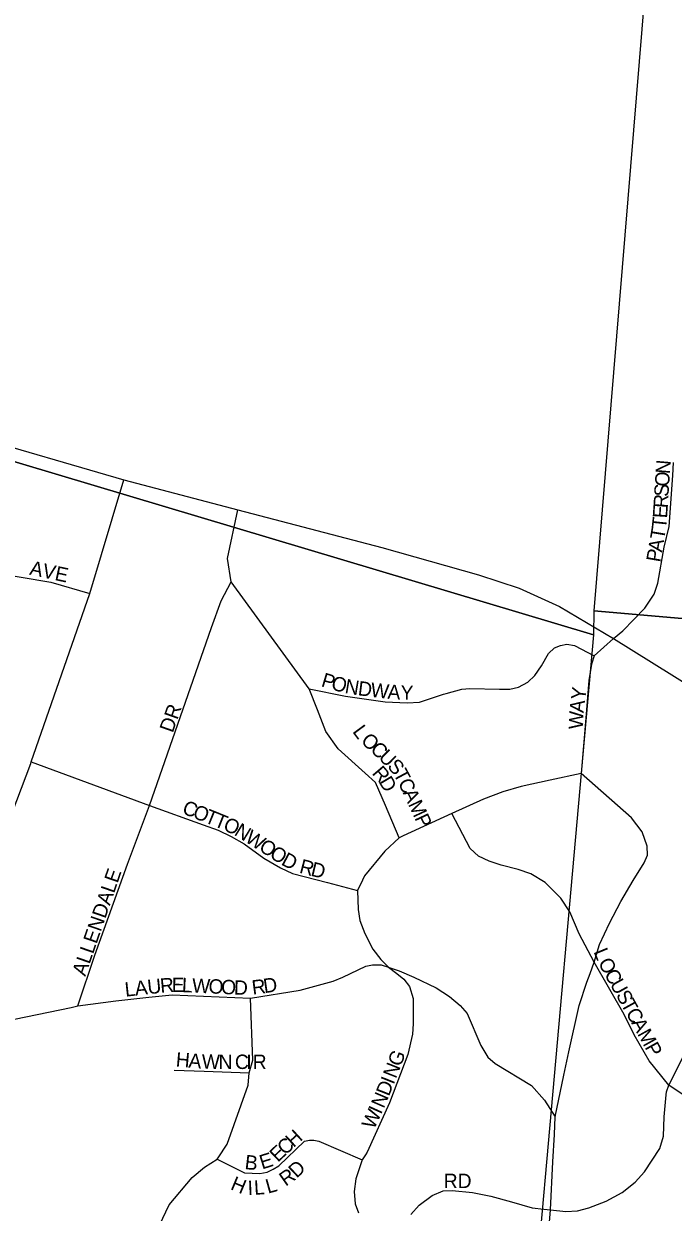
# Model space of a CAD drawing. Extents: x -209 to 4852, y 0 to 905.
# Drawn here: x 550.64 to 559.18, y 296.95 to 312.57 of the extents above; entities that cross this region are included whole.
import ezdxf

# ---------------------------------------------------------------- set-up
doc = ezdxf.new("R2010")
doc.units = 0
for name, color, linetype in [('GM_X_Airport_Location_Class_2', 7, 'Continuous'), ('GM_X_Airport_Location_Class_3', 7, 'Continuous'), ('GM_X_Minor_River', 7, 'Continuous')]:
    doc.layers.add(name, color=color, linetype=linetype)

msp = doc.modelspace()

# ---------------------------------------------------------------- linework, layer by layer
at = {"layer": 'GM_X_Airport_Location_Class_2'}
for points in [[(548.525, 307.589), (549.899, 307.171), (551.953, 306.575), (553.454, 306.181), (555.347, 305.684), (556.618, 305.327), (557.153, 305.149), (557.685, 304.91), (558.396, 304.487), (559.431, 303.846), (559.696, 303.716), (560.044, 303.613), (560.449, 303.573), (560.766, 303.576), (560.976, 303.613), (561.85, 303.84), (563.185, 304.193), (563.947, 304.283), (565.028, 304.262), (565.129, 304.259), (566.117, 304.211), (567.878, 304.065), (568.882, 303.995), (570.26, 303.866)], [(558.396, 304.487), (558.519, 304.587), (558.806, 304.885), (558.931, 305.069), (558.977, 305.215), (559.059, 305.688), (559.125, 305.96), (559.176, 306.632), (559.183, 306.8)], [(550.727, 302.846), (550.735, 302.866), (551.505, 305.081), (551.953, 306.575)], [(551.347, 299.657), (551.572, 300.324), (552, 301.522), (552.288, 302.293), (552.898, 304.039), (553.106, 304.634), (553.231, 304.985), (553.363, 305.232), (553.316, 305.54), (553.454, 306.181)], [(544.594, 304.586), (545.72, 304.515), (546.39, 304.501), (546.876, 304.584), (547.477, 304.777), (548.049, 305.045), (548.495, 305.231), (548.976, 305.321), (549.499, 305.381), (550.207, 305.361), (550.992, 305.229), (551.505, 305.081)], [(555.573, 301.869), (555.395, 302.294), (555.262, 302.597), (555.129, 302.717), (554.771, 303.036), (554.609, 303.264), (554.501, 303.55), (554.391, 303.826), (553.363, 305.232)], [(558.396, 304.487), (558.141, 304.261), (558.104, 304.152), (558.071, 303.936), (558.029, 303.44), (557.969, 302.715), (557.563, 302.627), (557.181, 302.543), (556.94, 302.473), (556.686, 302.378), (556.268, 302.188), (555.625, 301.893)], [(556.193, 303.765), (556.399, 303.82), (556.504, 303.831), (556.894, 303.82), (557.029, 303.82), (557.143, 303.848), (557.267, 303.915), (557.359, 304), (557.445, 304.127), (557.541, 304.289), (557.618, 304.365), (557.699, 304.397), (557.781, 304.412), (557.88, 304.394), (558.141, 304.261)], [(554.391, 303.826), (554.868, 303.73), (555.39, 303.655), (555.678, 303.643), (555.84, 303.651), (556.159, 303.756), (556.193, 303.765)], [(549.566, 299.305), (549.606, 299.452), (549.917, 300.6), (550.359, 301.871), (550.727, 302.846)], [(550.735, 302.866), (552.288, 302.293), (552.997, 302.037), (553.194, 301.967), (553.366, 301.887), (553.534, 301.788), (553.793, 301.602), (554.012, 301.474), (554.17, 301.401), (554.633, 301.279), (555.028, 301.176)], [(558.086, 300.086), (558.141, 300.235), (558.21, 300.465), (558.34, 300.745), (558.491, 301.032), (558.654, 301.307), (558.798, 301.539), (558.841, 301.639), (558.835, 301.759), (558.772, 301.948), (558.633, 302.131), (557.969, 302.715)], [(560.334, 298.043), (559.482, 298.376), (559.122, 298.617), (558.863, 298.935), (558.668, 299.277), (558.533, 299.547), (558.141, 300.235), (557.943, 300.606), (557.82, 300.894), (557.7, 301.074), (557.494, 301.28), (557.308, 301.396), (557.14, 301.453), (556.916, 301.507), (556.757, 301.563), (556.616, 301.627), (556.51, 301.728), (556.268, 302.188)], [(555.625, 301.893), (555.573, 301.869), (555.386, 301.692), (555.118, 301.369), (555.091, 301.311)], [(555.091, 301.311), (555.028, 301.176), (555.033, 300.927), (555.055, 300.78), (555.121, 300.609), (555.226, 300.402), (555.335, 300.267), (555.435, 300.167), (555.544, 300.084), (555.636, 300.008), (555.71, 299.913), (555.759, 299.754), (555.759, 299.422), (555.751, 299.288), (555.688, 299.019), (555.446, 298.382), (555.155, 297.737), (555.131, 297.7)], [(559.088, 298.491), (559.091, 298.528), (559.122, 298.617), (559.323, 299.017), (559.872, 299.995), (560.298, 300.757), (560.391, 300.94), (560.427, 301.12)], [(551.258, 299.638), (551.347, 299.657), (551.845, 299.723), (552.283, 299.771), (552.588, 299.805), (553.619, 299.762), (554.271, 299.867), (554.708, 299.984), (554.835, 300.035), (555.138, 300.179), (555.224, 300.199), (555.336, 300.196), (555.435, 300.167), (555.442, 300.165)], [(555.442, 300.165), (555.575, 300.121), (555.766, 300.035), (556.059, 299.896), (556.237, 299.784), (556.379, 299.664), (556.468, 299.558), (556.648, 299.136), (556.743, 298.983), (556.836, 298.902), (557.314, 298.614), (557.485, 298.418), (557.627, 298.2)], [(557.741, 298.747), (557.805, 299.053), (557.942, 299.664), (558.044, 299.97), (558.086, 300.086)], [(553.192, 297.662), (553.312, 297.839), (553.586, 298.618), (553.602, 298.779), (553.65, 298.944), (553.619, 299.762)], [(549.647, 299.454), (550.512, 299.486), (551.258, 299.638)], [(552.614, 298.814), (553.01, 298.8)], [(553.01, 298.8), (553.602, 298.779)], [(557.616, 297.967), (557.627, 298.2), (557.741, 298.747)], [(557.478, 296.987), (557.566, 296.978), (557.769, 296.955), (557.922, 296.965), (558.068, 297.004), (558.298, 297.092), (558.509, 297.204), (558.681, 297.34), (558.802, 297.478), (559.002, 297.783), (559.05, 297.945), (559.062, 298.199), (559.088, 298.491)], [(557.566, 296.979), (557.597, 297.607), (557.616, 297.967)], [(553.179, 297.643), (553.538, 297.462), (553.74, 297.453), (553.84, 297.474), (553.918, 297.51), (553.991, 297.558), (554.329, 297.881), (554.395, 297.893), (554.453, 297.893), (554.519, 297.878), (555.089, 297.634)], [(552.423, 296.776), (552.548, 297.042), (552.85, 297.404), (553.013, 297.537), (553.179, 297.643), (553.192, 297.662)], [(555.131, 297.7), (555.089, 297.634), (555.006, 297.385), (554.982, 297.219), (554.996, 297.055), (555.038, 296.937)], [(555.73, 296.914), (555.839, 297.037), (556.007, 297.166), (556.152, 297.226), (556.272, 297.23), (556.539, 297.204), (556.782, 297.159), (557.05, 297.084), (557.325, 297.004), (557.478, 296.987)], [(557.251, 294.826), (557.278, 294.935), (557.545, 296.711), (557.566, 296.978), (557.566, 296.979)]]:
    msp.add_lwpolyline(points, dxfattribs=at)
at = {"layer": 'GM_X_Minor_River'}
for points in [[(539.664, 315.099), (558.841, 313.406), (558.136, 304.853), (558.13, 304.535), (539.314, 310.159)], [(571.768, 303.667), (571.768, 312.203), (559.212, 313.354), (558.841, 313.406), (558.136, 304.853)], [(539.314, 310.159), (558.13, 304.535), (556.318, 284.232), (537.772, 289.267)], [(571.768, 283.238), (571.768, 303.667), (558.136, 304.853), (558.13, 304.535), (556.318, 284.232)]]:
    msp.add_lwpolyline(points, close=True, dxfattribs=at)

# ---------------------------------------------------------------- texts
at = {"layer": 'GM_X_Airport_Location_Class_3'}
for s, height, rotation, p in [('N', 0.189, 85.2509, (559.135, 306.646)), ('O', 0.189, 86.3673, (559.125, 306.481)), ('S', 0.189, 86.3685, (559.116, 306.348)), ('E', 0.189, 86.3543, (559.098, 306.065)), ('R', 0.189, 86.3555, (559.107, 306.198)), ('T', 0.189, 84.1092, (559.084, 305.924)), ('T', 0.189, 80.5341, (559.06, 305.78)), ('A', 0.189, 80.3085, (559.032, 305.615)), ('P', 0.189, 80.2816, (559.009, 305.483)), ('AVE', 0.1894, 347.9058, (550.703, 305.329)), ('P', 0.189, 343.4578, (554.538, 303.861)), ('O', 0.189, 343.982, (554.668, 303.823)), ('N', 0.189, 350.4677, (554.851, 303.772)), ('D', 0.189, 353.0736, (555.025, 303.743)), ('W', 0.189, 353.3064, (555.191, 303.723)), ('A', 0.189, 356.2773, (555.417, 303.696)), ('Y', 0.189, 358.1913, (555.59, 303.685)), ('Y', 0.189, 82.8777, (558.02, 303.67)), ('DR', 0.1894, 70.5721, (552.595, 303.239)), ('A', 0.189, 83.1216, (558, 303.504)), ('W', 0.189, 87.7799, (557.992, 303.292)), ('L', 0.189, 306.7606, (554.953, 303.263)), ('O', 0.189, 317.8856, (555.06, 303.127)), ('C', 0.189, 317.2673, (555.183, 303.015)), ('U', 0.189, 315.2937, (555.292, 302.915)), ('R', 0.189, 310.4275, (555.208, 302.713)), ('S', 0.189, 313.2421, (555.409, 302.799)), ('T', 0.189, 298.2878, (555.493, 302.712)), ('D', 0.189, 300.6152, (555.3, 302.606)), ('C', 0.189, 295.0228, (555.555, 302.597)), ('A', 0.189, 295.0011, (555.618, 302.461)), ('C', 0.189, 338.1219, (552.707, 302.194)), ('M', 0.189, 295.0183, (555.689, 302.31)), ('O', 0.189, 338.0931, (552.846, 302.138)), ('T', 0.189, 338.1155, (553.001, 302.076)), ('T', 0.189, 338.1323, (553.125, 302.026)), ('P', 0.189, 295.0256, (555.773, 302.129)), ('O', 0.189, 335.6736, (553.246, 301.977)), ('N', 0.189, 328.6689, (553.393, 301.911)), ('W', 0.189, 327.4012, (553.534, 301.825)), ('O', 0.189, 327.419, (553.717, 301.709)), ('O', 0.189, 327.4132, (553.857, 301.619)), ('D', 0.189, 331.7329, (554.011, 301.521)), ('R', 0.189, 345.293, (554.251, 301.41)), ('D', 0.189, 346.4563, (554.401, 301.371)), ('ALLENDALE', 0.1894, 70.906, (551.445, 300.039)), ('L', 0.189, 292.2123, (558.129, 300.372)), ('O', 0.189, 297.7746, (558.187, 300.23)), ('C', 0.189, 298.9765, (558.267, 300.079)), ('L', 0.189, 6.1048, (551.974, 299.779)), ('A', 0.189, 6.0868, (552.106, 299.793)), ('U', 0.189, 6.1071, (552.272, 299.811)), ('R', 0.189, 4.935, (552.437, 299.829)), ('E', 0.189, 359.3989, (552.582, 299.842)), ('L', 0.189, 357.3763, (552.713, 299.84)), ('W', 0.189, 357.2585, (552.846, 299.834)), ('O', 0.189, 357.2446, (553.063, 299.824)), ('O', 0.189, 357.2446, (553.229, 299.816)), ('D', 0.189, 357.8649, (553.398, 299.808)), ('R', 0.189, 7.1641, (553.648, 299.805)), ('D', 0.189, 8.4316, (553.801, 299.825)), ('U', 0.189, 298.9803, (558.34, 299.948)), ('S', 0.189, 298.9724, (558.421, 299.802)), ('T', 0.189, 298.9724, (558.485, 299.685)), ('C', 0.189, 298.9976, (558.55, 299.568)), ('A', 0.189, 298.9803, (558.623, 299.437)), ('M', 0.189, 298.9801, (558.703, 299.291)), ('P', 0.189, 298.978, (558.8, 299.116)), ('H', 0.189, 355.1202, (552.631, 298.863)), ('A', 0.189, 355.3082, (552.798, 298.848)), ('G', 0.189, 68.4597, (555.592, 298.849)), ('W', 0.189, 358.762, (552.976, 298.834)), ('N', 0.189, 0.0154, (553.198, 298.829)), ('C', 0.189, 0, (553.414, 298.829)), ('I', 0.189, 0, (553.564, 298.829)), ('R', 0.189, 0, (553.648, 298.829)), ('N', 0.189, 68.4597, (555.531, 298.694)), ('I', 0.189, 68.4624, (555.501, 298.616)), ('D', 0.189, 68.4241, (555.439, 298.461)), ('N', 0.189, 66.7284, (555.371, 298.302)), ('W', 0.189, 65.5936, (555.245, 298.025)), ('I', 0.189, 65.6201, (555.335, 298.223)), ('H', 0.189, 42.5883, (554.185, 297.788)), ('E', 0.189, 43.7674, (553.979, 297.595)), ('C', 0.189, 42.7327, (554.075, 297.686)), ('B', 0.189, 353.5257, (553.536, 297.515)), ('E', 0.189, 17.4654, (553.771, 297.507)), ('R', 0.189, 35.0435, (554.081, 297.28)), ('D', 0.189, 43.5831, (554.227, 297.386)), ('H', 0.189, 337.3869, (553.344, 297.251)), ('I', 0.189, 2.4625, (553.585, 297.171)), ('L', 0.189, 3.0657, (553.67, 297.175)), ('L', 0.189, 15.7015, (553.848, 297.189)), ('RD', 0.1894, 0, (556.161, 297.263))]:
    msp.add_text(s, height=height, rotation=rotation, dxfattribs=at).set_placement(p)

doc.saveas('drawing.dxf')
